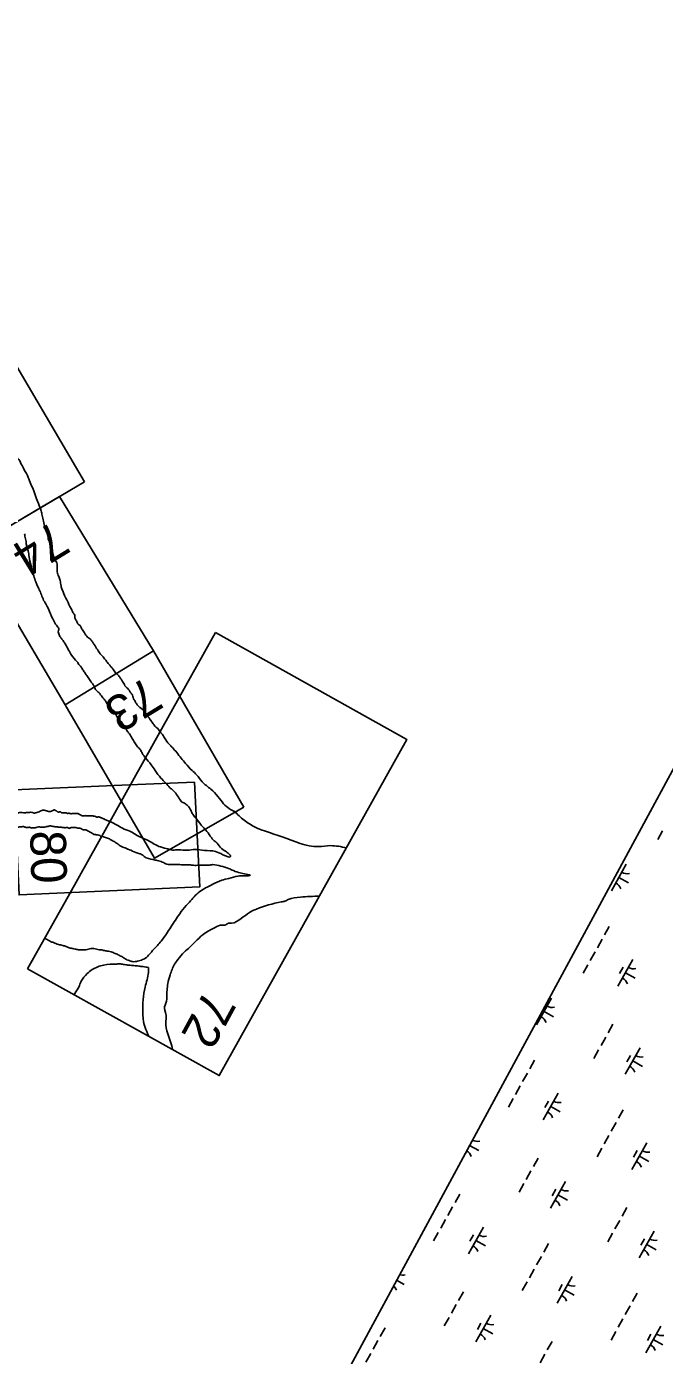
# Model space of a CAD drawing. Extents: x 3923531 to 3943530, y 207391 to 229799.
# Drawn here: x 3928152 to 3929196, y 216516 to 218692 of the extents above; entities that cross this region are included whole.
import ezdxf

# ---------------------------------------------------------------- set-up
doc = ezdxf.new("R2010")
doc.units = 0
for name, color, linetype in [('V-ANNO-NPLT', 7, 'Continuous'), ('V-GRID-FRAM', 7, 'Continuous'), ('V-WETL-SWMP', 7, 'Continuous')]:
    doc.layers.add(name, color=color, linetype=linetype)

msp = doc.modelspace()

# ---------------------------------------------------------------- linework, layer by layer
at = {"layer": 'V-ANNO-NPLT'}
for p, q in [((3928360.1, 217670), (3928215.6, 217581.4)), ((3928162.6, 217162.8), (3928161.5, 217162.6)), ((3928230.3, 217107), (3928237.7, 217119.5))]:
    msp.add_line(p, q, dxfattribs=at)
for points in [[(3928247.1, 217946.4), (3928106.5, 218185.6)], [(3928106.4, 217863.6), (3928247.1, 217946.4)], [(3928206.3, 217922.4), (3928063.7, 217838.5), (3928215.6, 217581.4)], [(3928206.3, 217922.4), (3928360.1, 217670)], [(3928461.6, 217699.9), (3928775, 217524.6), (3928467.6, 216974.4), (3928154, 217149.4)], [(3928402, 217593.3), (3928461.6, 217699.9)], [(3928360.1, 217670), (3928215.6, 217581.4), (3928361.7, 217330.3), (3928507.7, 217413.9)], [(3928507.7, 217413.9), (3928360.1, 217670)], [(3928222.8, 217272.5), (3928402, 217593.3)], [(3928320.8, 217450.5), (3928132, 217442.5)], [(3928132, 217442.5), (3928140, 217270.3), (3928435.7, 217283.4), (3928431.6, 217368)], [(3928427.3, 217455.1), (3928320.8, 217450.5)], [(3928431.6, 217368), (3928427.3, 217455.1)], [(3928154, 217149.4), (3928222.8, 217272.5)]]:
    msp.add_lwpolyline(points, dxfattribs=at)
for points in [[(3928174.6, 217903.9), (3928168.7, 217918.7), (3928164, 217931.6), (3928159.3, 217942.9), (3928155, 217953.9), (3928148.4, 217966.4), (3928143.6, 217975.6), (3928137.7, 217984.9), (3928134.8, 217987.1), (3928132.5, 217993.3), (3928130.8, 217996.9), (3928125.1, 218004.5), (3928117.1, 218012.9), (3928105.1, 218029)], [(3928217.9, 217753.4), (3928213.4, 217763.1), (3928210.7, 217769.8), (3928208.7, 217776), (3928207.3, 217785), (3928205, 217791.4), (3928202.3, 217799.1), (3928202.2, 217805.8), (3928201.7, 217813.7), (3928198.1, 217819.8), (3928195.4, 217830), (3928192.4, 217838.9), (3928191, 217846.8), (3928188.4, 217850.3), (3928187.5, 217856.5), (3928182.3, 217871.2), (3928180, 217882.2), (3928177.9, 217891.6), (3928176, 217898.8), (3928174.6, 217903.9)], [(3928197.2, 217718), (3928189.5, 217734.4), (3928184.9, 217744.7), (3928180.2, 217752.5), (3928176.5, 217761.8), (3928173.1, 217769.9), (3928169.6, 217777), (3928167.4, 217782.8), (3928163.9, 217792.5), (3928160.6, 217805.1), (3928156.8, 217820.5), (3928155.3, 217831), (3928152.2, 217841.5), (3928151.3, 217848.6), (3928149.5, 217857.8), (3928149, 217861.2)], [(3928286.8, 217648.2), (3928282.9, 217653), (3928278.9, 217658.3), (3928272.9, 217664.8), (3928268.2, 217671.8), (3928263, 217680.2), (3928260, 217684.5), (3928256.7, 217689), (3928250.6, 217693.7), (3928246, 217701), (3928242, 217707.2), (3928239.7, 217711.1), (3928236.3, 217713.9), (3928233.8, 217719.1), (3928231.2, 217724), (3928231.4, 217726.4), (3928228.9, 217731.6), (3928226.3, 217736.5), (3928223.1, 217742.6), (3928221.1, 217747.1), (3928219.2, 217751.2), (3928217.9, 217753.4)], [(3928215.4, 217681.4), (3928214.4, 217682.9), (3928211, 217687.8), (3928207.7, 217692.3), (3928204.9, 217697.7), (3928204, 217701.2), (3928204.9, 217704.8), (3928202.4, 217710.1), (3928199.7, 217713.3), (3928197.2, 217718)], [(3928215.4, 217681.4), (3928221.1, 217670.9), (3928225.9, 217662.6), (3928234.7, 217652.2)], [(3928263.2, 217610.6), (3928260.7, 217615.5), (3928257.2, 217619.7), (3928253, 217626.3), (3928248.8, 217632.1), (3928245.3, 217637.5), (3928241.4, 217643.2), (3928236.9, 217649.2), (3928234.8, 217652.1), (3928234.7, 217652.2)], [(3928370.8, 217537.4), (3928369.3, 217539.6), (3928367.2, 217542.5), (3928365.2, 217544.1), (3928363.3, 217545.2), (3928361.2, 217548.1), (3928359.6, 217550.3), (3928357.3, 217553.7), (3928355.4, 217556.1), (3928353, 217560), (3928350.5, 217562.3), (3928347.6, 217567.4), (3928345.3, 217570), (3928342.5, 217573.7), (3928338.6, 217576.4), (3928334.3, 217580.6), (3928331.3, 217584.9), (3928328.5, 217589.5), (3928326.6, 217593.5), (3928325.4, 217597.2), (3928322.7, 217601.3), (3928320, 217605.3), (3928317.3, 217608.6), (3928314.5, 217611.1), (3928312.3, 217614.5), (3928310.2, 217618.2), (3928308, 217621.6), (3928305.6, 217625.5), (3928302, 217630.1), (3928297.9, 217633.8), (3928293.2, 217640.3), (3928290, 217644.3), (3928286.8, 217648.2)], [(3928347, 217494.7), (3928341.4, 217502.4), (3928338.6, 217507.8), (3928333.9, 217512.7), (3928329.7, 217519.3), (3928325.1, 217526.6), (3928320.5, 217533.9), (3928317.7, 217537.7), (3928312.8, 217545.2), (3928308.8, 217551.3), (3928305, 217556.4), (3928301.3, 217560.3), (3928298.8, 217564.7), (3928296.7, 217568.9), (3928294.7, 217572.1), (3928290.5, 217574.2), (3928288.1, 217578.1), (3928285.4, 217581.3), (3928283.2, 217584.7), (3928280.4, 217589.3), (3928276.1, 217594.3), (3928270.5, 217601.4), (3928266, 217605.2), (3928263.2, 217610.6)], [(3928500, 217399.6), (3928492.4, 217406.7), (3928484.3, 217411.4), (3928474.8, 217419.6), (3928465.5, 217431.3), (3928453.8, 217443.5), (3928439.9, 217455.2), (3928430.6, 217466.9), (3928423.1, 217473.9), (3928412.5, 217485.4), (3928405.3, 217494.2), (3928398, 217503.3), (3928391.1, 217511.4), (3928387.2, 217515.4), (3928380.4, 217523.9), (3928375.7, 217531.1), (3928370.8, 217537.4)], [(3928347, 217494.7), (3928356, 217483.5), (3928363, 217474), (3928372, 217461.6), (3928380, 217453.4), (3928386.9, 217445.7), (3928391.6, 217441.9), (3928397.7, 217434.8), (3928403.6, 217426), (3928406.1, 217422.7), (3928410.6, 217420.3), (3928416.3, 217416.1), (3928421, 217408.9), (3928423.5, 217403.8), (3928427.9, 217397.7), (3928435.6, 217387.8), (3928440.5, 217381.7), (3928447.3, 217374.3), (3928454.9, 217364), (3928461.1, 217357.7), (3928462, 217357.1), (3928469.2, 217348.5), (3928477.8, 217341.7), (3928483.5, 217337.5), (3928486.3, 217333.2), (3928473.6, 217336.1), (3928461.5, 217341.4), (3928443.3, 217343.2), (3928428.3, 217344.7), (3928415.1, 217343.3), (3928401.3, 217344.2), (3928391.2, 217343.8), (3928380.9, 217346.2), (3928368.7, 217349.8), (3928348.9, 217360.4), (3928338.7, 217364.6), (3928330.1, 217369.5), (3928321.3, 217374.7), (3928309.2, 217379.3), (3928300.5, 217384.5), (3928288.3, 217390.8)], [(3928165.2, 217404.2), (3928165, 217404.1), (3928163.6, 217404.6), (3928162.5, 217405), (3928158.9, 217405.5), (3928154.9, 217405.3), (3928151.8, 217405.2), (3928149.4, 217404.7), (3928147.3, 217404.9), (3928142.4, 217405), (3928139.2, 217404.6), (3928136.7, 217403.3), (3928134.4, 217403.6), (3928132.1, 217403.3), (3928130.9, 217403.1), (3928128.4, 217402.1), (3928125.3, 217402), (3928122.4, 217402.3), (3928114.7, 217402.7), (3928109.8, 217403.7), (3928104.4, 217402.9), (3928101.1, 217402.9), (3928097.6, 217402.5), (3928090.6, 217402.4), (3928086.6, 217402.6), (3928083.4, 217402.8), (3928078.1, 217402.6), (3928076.6, 217402.4), (3928075, 217401.1), (3928072.2, 217400.6)], [(3928178.5, 217408.9), (3928175.6, 217407.8), (3928172.9, 217406.5), (3928168.8, 217405.2), (3928166.2, 217404.5), (3928165.2, 217404.2)], [(3928202, 217407.3), (3928200.4, 217408.1), (3928199.3, 217408.7), (3928197.6, 217409.4), (3928196.3, 217409.1), (3928194.6, 217408.1), (3928193.2, 217407.6), (3928192.1, 217407.1), (3928189.2, 217406.9), (3928187.6, 217407), (3928186.3, 217407.5), (3928184.4, 217408), (3928183.1, 217408.5), (3928181.6, 217408.9), (3928180.1, 217409.2), (3928178.5, 217408.9)], [(3928226.3, 217403.4), (3928225.4, 217403.2), (3928224.1, 217403.4), (3928223, 217403.8), (3928221.2, 217404), (3928220.9, 217403.9), (3928219.6, 217403.6), (3928219.1, 217403.3), (3928218.2, 217404.1), (3928215.4, 217404.4), (3928213.1, 217404.6), (3928208.9, 217405.1), (3928208.4, 217406), (3928207.1, 217406.2), (3928205.1, 217406), (3928203.7, 217406), (3928203.1, 217406.4), (3928202, 217407.3)], [(3928237.1, 217403.2), (3928234.7, 217403.4), (3928231.9, 217403.4), (3928228.8, 217403.6), (3928226.3, 217403.4)], [(3928288.3, 217390.8), (3928283.1, 217392.4), (3928280.6, 217393.8), (3928278.7, 217394.7), (3928276.8, 217395.2), (3928275.2, 217396.2), (3928273.4, 217396.9), (3928271.6, 217397.7), (3928269.3, 217397.9), (3928267.3, 217397.7), (3928264.8, 217398.6), (3928261.8, 217399.3), (3928259.8, 217399.6), (3928256.9, 217399.7), (3928254.4, 217399.7), (3928252.7, 217399.6), (3928249.7, 217400), (3928247.4, 217400), (3928242.1, 217400.3), (3928239.1, 217402.1), (3928237.1, 217403.2)], [(3928676.1, 217347.3), (3928649.7, 217350.9), (3928629.9, 217349.4), (3928570.9, 217365.3), (3928517.2, 217386.5), (3928500, 217399.6)], [(3928676, 217347.3), (3928649.7, 217350.9), (3928629.9, 217349.4), (3928570.9, 217365.3), (3928517.2, 217386.5), (3928500, 217399.6)], [(3928183.6, 217381.7), (3928179.7, 217381.1), (3928178.2, 217381.4), (3928176.4, 217381.3), (3928173.3, 217381.6), (3928171.5, 217381.5), (3928167.8, 217380.5), (3928161.3, 217379.9), (3928159.3, 217379.9), (3928157.4, 217381.1), (3928154.9, 217380.8), (3928151.7, 217380.9), (3928149.6, 217381.2), (3928147.5, 217382.2), (3928144.6, 217381.6), (3928142.6, 217381.6), (3928140.7, 217381.8), (3928137.1, 217380.7), (3928134.1, 217380.4), (3928131.9, 217380.2), (3928128.8, 217380.3), (3928127, 217380.2), (3928122.7, 217379.8), (3928118.4, 217378.5), (3928114.4, 217379.1), (3928110.3, 217379.5), (3928105.2, 217379.3), (3928101.8, 217378.9), (3928097.1, 217378.8), (3928092.8, 217378.9), (3928090.4, 217378.3)], [(3928274.8, 217366), (3928272.2, 217367.3), (3928268.5, 217368.5), (3928266.2, 217368.7), (3928263.7, 217369.3), (3928261.6, 217369.6), (3928259.5, 217371.1), (3928257.4, 217372.4), (3928255.1, 217373.4), (3928252.2, 217375.4), (3928250.1, 217376.3), (3928248, 217376.7), (3928245.5, 217377), (3928242.3, 217378.5), (3928239.3, 217379.7), (3928236, 217379.6), (3928232.7, 217380.4), (3928229.1, 217380.7), (3928226.8, 217380.6), (3928224, 217379.9), (3928222.4, 217379.1), (3928220.3, 217380), (3928218.7, 217380.7), (3928216.7, 217380.4), (3928214.9, 217380.3), (3928212.8, 217380.6), (3928210.4, 217380.9), (3928207.4, 217381.2), (3928205.3, 217381.2), (3928202.7, 217381.6), (3928195.5, 217382.3), (3928190.2, 217383.1), (3928187.6, 217382.3), (3928185.8, 217382.5), (3928183.6, 217381.7)], [(3928274.8, 217366), (3928287.9, 217361.9), (3928292.6, 217359.2), (3928298.6, 217355.7), (3928305.5, 217350.7), (3928309.8, 217348.7), (3928313.6, 217347.1), (3928322.8, 217343.3), (3928334.3, 217338.5), (3928340.4, 217336.7), (3928344.7, 217333.3), (3928359.5, 217328), (3928366.2, 217326.7), (3928374.3, 217324.1), (3928382.1, 217320.5), (3928390.7, 217319.9), (3928396.2, 217320), (3928403.2, 217319.8), (3928412.6, 217319.3), (3928420.8, 217319.3), (3928427.4, 217318.6), (3928436.8, 217319.1), (3928444.8, 217318.9), (3928450.7, 217319), (3928457, 217319.8), (3928470, 217317.6), (3928483, 217313.6), (3928490.7, 217310), (3928501.9, 217306.2), (3928511.8, 217304.2), (3928518.5, 217302.6), (3928508.6, 217301.4), (3928498.6, 217301.1), (3928483.3, 217297.3), (3928471.7, 217294.2), (3928457, 217287.6), (3928438.7, 217277.6), (3928428.4, 217269.3), (3928420.6, 217260.4), (3928413.5, 217252.9), (3928402.9, 217239.4), (3928396, 217229), (3928388.3, 217217.4), (3928381.1, 217206.4), (3928372.3, 217194.5), (3928366.3, 217187.3), (3928362.6, 217183.4)], [(3928631.8, 217268.4), (3928600.4, 217266.6), (3928580.7, 217262.6), (3928575.1, 217260.1), (3928569.2, 217258.7), (3928528.5, 217247.2), (3928517.4, 217241.6), (3928503.5, 217231.6), (3928487.6, 217224.1), (3928482.3, 217223.8), (3928476.8, 217220.7), (3928471.7, 217220.8), (3928461.2, 217217.2), (3928444.2, 217207.6), (3928419.6, 217184.9), (3928410.3, 217176.5), (3928400, 217164.6), (3928394.5, 217156.9), (3928387.2, 217139.2), (3928383.3, 217125.1), (3928382.3, 217114.5), (3928381.8, 217109.2), (3928381.3, 217096.1), (3928378, 217084), (3928379.9, 217077.9), (3928380.3, 217057.8), (3928391.3, 217018), (3928391.5, 217016.8)], [(3928188.6, 217195.8), (3928186.1, 217197.1), (3928184.6, 217197.9), (3928181.9, 217199.3)], [(3928241.1, 217180.2), (3928237.1, 217180.6), (3928231.5, 217181.6), (3928228.1, 217182.4), (3928225.3, 217182.9), (3928222.1, 217183.4), (3928216.9, 217186), (3928211.4, 217187.3), (3928207.6, 217188.4), (3928204.4, 217189.1), (3928196.3, 217192.2), (3928191.4, 217194.1), (3928188.6, 217195.8)], [(3928293.9, 217175.8), (3928290.7, 217177), (3928286.1, 217178.1), (3928282.6, 217178.7), (3928279.9, 217179.1), (3928276.8, 217179.9), (3928271.3, 217180.6), (3928266.8, 217181.5), (3928261.9, 217182.6), (3928257.7, 217182.7), (3928253.4, 217181.4), (3928249.4, 217180.4), (3928245.7, 217180.1), (3928242.6, 217180.3), (3928241.1, 217180.2)], [(3928362.6, 217183.4), (3928359.3, 217180.3), (3928355.6, 217175.3), (3928354.4, 217174.1), (3928351.7, 217171.6), (3928349.5, 217168.7), (3928345.7, 217166.2), (3928342.2, 217164.4), (3928338.1, 217162.7), (3928333.7, 217161.6), (3928330.1, 217161), (3928325.8, 217161.2), (3928320.1, 217162.8), (3928316.6, 217164), (3928312.5, 217166.6), (3928306.7, 217170), (3928303.6, 217171.6), (3928297, 217174.5), (3928293.9, 217175.8)], [(3928237.7, 217119.5), (3928241.8, 217128.8), (3928251.5, 217141.5), (3928259.8, 217148.1), (3928278.5, 217155.5), (3928300.1, 217157.1)], [(3928351.9, 217151.5), (3928343.1, 217152.9), (3928335.9, 217153.7), (3928327.9, 217154.5), (3928319.9, 217155.3), (3928312.7, 217156.3), (3928306.2, 217157.2), (3928300.1, 217157.1)], [(3928351.9, 217151.5), (3928351.7, 217143.3), (3928346.2, 217119.4), (3928342.6, 217077.9), (3928343.2, 217066.9), (3928351.8, 217040), (3928351.9, 217039.8)]]:
    msp.add_spline(points, degree=3, dxfattribs=at)
at = {"layer": 'V-GRID-FRAM'}
msp.add_lwpolyline([(3941569.4, 222286.8), (3934196.5, 209089.1), (3926890.1, 213186.2), (3934009.8, 226348.1), (3941569.4, 222286.8)], dxfattribs=at)
at = {"layer": 'V-WETL-SWMP'}
for p, q in [((3927557.6, 214420.2), (3930423.1, 219717.6)), ((3929193.5, 217375), (3929185.7, 217361)), ((3929134, 217320.4), (3929109.6, 217276.8)), ((3929121.8, 217298.6), (3929137.5, 217289.8)), ((3929106.2, 217218.8), (3929098.4, 217204.8)), ((3929094.5, 217197.8), (3929086.7, 217183.8)), ((3929071.1, 217155.9), (3929063.3, 217141.9)), ((3929082.8, 217176.9), (3929075, 217162.9)), ((3929144.8, 217164.7), (3929120.4, 217121)), ((3929128.8, 217151.8), (3929122.9, 217141.4)), ((3929132.6, 217142.8), (3929148.3, 217134.1)), ((3929011.6, 217101.4), (3928987.2, 217057.7)), ((3928999.4, 217079.5), (3929015.1, 217070.8)), ((3929112.1, 217058.6), (3929104.3, 217044.6)), ((3929100.4, 217037.6), (3929092.6, 217023.7)), ((3929088.7, 217016.7), (3929080.9, 217002.7)), ((3929156.8, 217020.2), (3929132.4, 216976.6)), ((3929140.8, 217007.4), (3929134.9, 216996.9)), ((3928983.8, 216999.7), (3928976, 216985.7)), ((3929144.6, 216998.4), (3929160.3, 216989.6)), ((3928972.1, 216978.7), (3928964.3, 216964.8)), ((3928960.4, 216957.8), (3928952.6, 216943.8)), ((3929022.4, 216945.6), (3928998, 216901.9)), ((3928948.7, 216936.8), (3928940.9, 216922.9)), ((3929006.4, 216932.8), (3929000.5, 216922.3)), ((3929010.2, 216923.8), (3929025.9, 216915)), ((3929129.1, 216918.6), (3929121.2, 216904.6)), ((3929117.3, 216897.6), (3929109.5, 216883.6)), ((3929105.6, 216876.6), (3929097.8, 216862.7)), ((3928877.4, 216860.2), (3928892.7, 216851.7)), ((3929093.9, 216855.7), (3929086.1, 216841.7)), ((3929167.6, 216864.5), (3929143.2, 216820.8)), ((3929151.6, 216851.6), (3929145.7, 216841.2)), ((3928989.7, 216839.5), (3928981.9, 216825.5)), ((3929155.4, 216842.6), (3929171.1, 216833.9)), ((3928978, 216818.6), (3928970.2, 216804.6)), ((3928966.3, 216797.6), (3928958.5, 216783.6)), ((3929034.4, 216801.1), (3929010, 216757.5)), ((3929018.4, 216788.3), (3929012.5, 216777.8)), ((3928861.4, 216780.6), (3928853.6, 216766.6)), ((3929022.2, 216779.3), (3929037.9, 216770.5)), ((3928849.7, 216759.6), (3928841.9, 216745.7)), ((3929134.9, 216758.4), (3929127.1, 216744.4)), ((3928838, 216738.7), (3928830.2, 216724.7)), ((3928900, 216726.5), (3928875.6, 216682.9)), ((3929123.2, 216737.4), (3929115.4, 216723.5)), ((3928826.3, 216717.7), (3928818.5, 216703.8)), ((3928884, 216713.7), (3928878.1, 216703.2)), ((3928887.8, 216704.7), (3928903.5, 216695.9)), ((3929006.7, 216699.5), (3928998.9, 216685.5)), ((3929111.5, 216716.5), (3929103.7, 216702.5)), ((3929179.6, 216720), (3929155.2, 216676.4)), ((3929163.6, 216707.2), (3929157.8, 216696.7)), ((3928995, 216678.5), (3928987.1, 216664.5)), ((3929167.4, 216698.2), (3929183.1, 216689.4)), ((3928983.2, 216657.6), (3928975.4, 216643.6)), ((3928758, 216639.4), (3928770.3, 216632.6)), ((3928971.5, 216636.6), (3928963.7, 216622.6)), ((3929045.2, 216645.4), (3929020.8, 216601.7)), ((3928867.3, 216620.4), (3928859.5, 216606.5)), ((3929029.2, 216632.6), (3929023.4, 216622.1)), ((3929033, 216623.6), (3929048.7, 216614.8)), ((3929151.9, 216618.3), (3929144.1, 216604.4)), ((3928855.6, 216599.5), (3928847.8, 216585.5)), ((3929140.2, 216597.4), (3929132.4, 216583.4)), ((3928843.9, 216578.5), (3928836.1, 216564.6)), ((3928912, 216582.1), (3928887.6, 216538.4)), ((3928896, 216569.2), (3928890.2, 216558.8)), ((3929128.5, 216576.4), (3929120.7, 216562.5)), ((3928739.1, 216561.5), (3928731.2, 216547.5)), ((3928899.8, 216560.2), (3928915.5, 216551.5)), ((3929116.8, 216555.5), (3929109, 216541.5)), ((3929190.4, 216564.3), (3929166, 216520.6)), ((3929174.4, 216551.4), (3929168.6, 216541)), ((3928727.3, 216540.6), (3928719.5, 216526.6)), ((3929012.5, 216539.3), (3929004.7, 216525.3)), ((3929178.2, 216542.4), (3929193.9, 216533.6)), ((3928715.6, 216519.6), (3928707.8, 216505.6)), ((3929000.8, 216518.4), (3928993, 216504.4))]:
    msp.add_line(p, q, dxfattribs=at)
for centre, start, end in [((3929108.5, 217274.4), 20.0381, 61.5817), ((3929135.5, 217322.6), 240.0381, 281.5817), ((3929119.3, 217118.6), 20.0381, 61.5817), ((3929146.3, 217166.8), 240.0381, 281.5817), ((3928986.1, 217055.3), 20.0381, 61.5817), ((3929013.1, 217103.5), 240.0381, 281.5817), ((3929158.3, 217022.4), 240.0381, 281.5817), ((3929131.3, 216974.2), 20.0381, 61.5817), ((3929023.9, 216947.8), 240.0381, 281.5817), ((3928996.9, 216899.5), 20.0381, 61.5817), ((3928863.7, 216836.2), 20.0381, 59.4542), ((3928890.7, 216884.4), 241.2806, 281.5817), ((3929169.1, 216866.6), 240.0381, 281.5817), ((3929142.1, 216818.4), 20.0381, 61.5817), ((3929035.9, 216803.3), 240.0381, 281.5817), ((3929008.9, 216755.1), 20.0381, 61.5817), ((3928901.5, 216728.7), 240.0381, 281.5817), ((3929181.1, 216722.2), 240.0381, 281.5817), ((3928874.5, 216680.4), 20.0381, 61.5817), ((3929154.2, 216674), 20.0381, 61.5817), ((3928768.3, 216665.4), 252.446, 281.5817), ((3928741.3, 216617.1), 20.0381, 48.2336), ((3929019.8, 216599.3), 20.0381, 61.5817), ((3929046.7, 216647.5), 240.0381, 281.5817), ((3928913.5, 216584.2), 240.0381, 281.5817), ((3928886.6, 216536), 20.0381, 61.5817), ((3929191.9, 216566.4), 240.0381, 281.5817), ((3929165, 216518.2), 20.0381, 61.5817)]:
    msp.add_arc(centre, 17.6, start, end, dxfattribs=at)

# ---------------------------------------------------------------- texts
at = {"layer": 'V-ANNO-NPLT'}
for s, rotation, p in [('74', 211.5218, (3928196.8, 217884)), ('73', 211.5218, (3928349.1, 217629.2)), ('80', 271.5218, (3928157.9, 217375.1)), ('72', 241.5218, (3928445.5, 217118))]:
    msp.add_text(s, height=58.5, rotation=rotation, dxfattribs=at).set_placement(p)

doc.saveas('drawing.dxf')
